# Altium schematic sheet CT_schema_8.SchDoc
size 274 x 160 mm
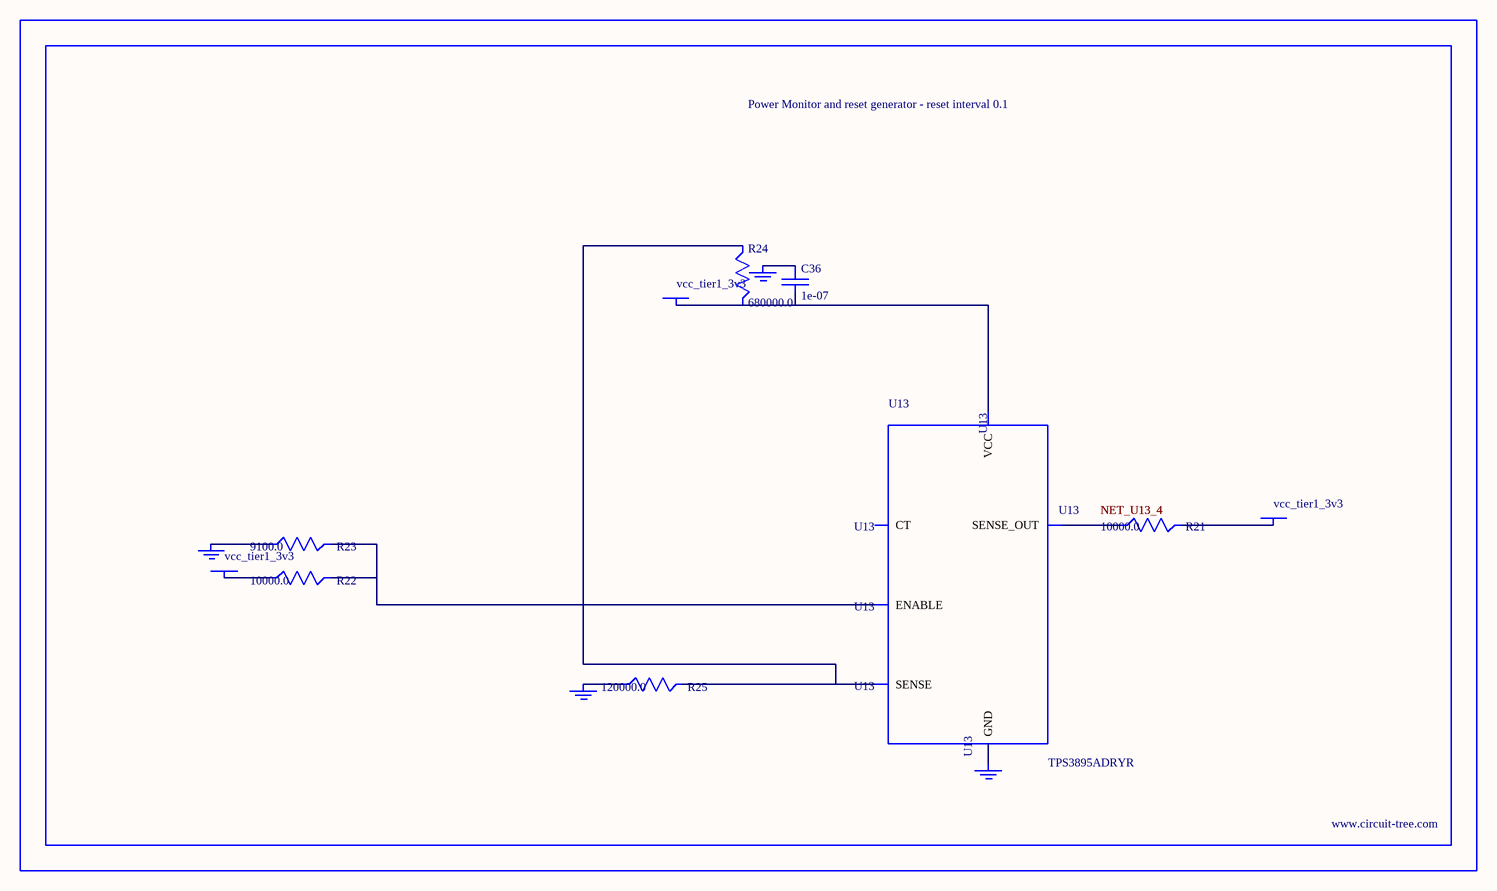
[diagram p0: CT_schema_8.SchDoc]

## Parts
BORDER7  (no value)
C36  1e-07  [C0402]
GND_INSTANCE_7_0  (no value)
GND_INSTANCE_7_1  (no value)
GND_INSTANCE_7_2  (no value)
GND_INSTANCE_7_3  (no value)
POWER_INSTANCE_7_0  vcc_tier1_3v3
POWER_INSTANCE_7_1  vcc_tier1_3v3
POWER_INSTANCE_7_2  vcc_tier1_3v3
R21  10000.0  [R0603]
R22  10000.0  [R0603]
R23  9100.0  [R0603]
R24  680000.0  [R0603]
R25  120000.0  [R0603]
U13  TPS3895ADRYR  [SON-6]

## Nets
NetC36_1: C36.1 GND_INSTANCE_7_2.0(GND)
NetC36_2: C36.2 POWER_INSTANCE_7_2.0(PWR) R24.2 U13.6(VCC)
NetGND_INSTANCE_7_0_0: GND_INSTANCE_7_0.0(GND) R23.1
NetGND_INSTANCE_7_1_0: GND_INSTANCE_7_1.0(GND) R25.1
NetGND_INSTANCE_7_3_0: GND_INSTANCE_7_3.0(GND) U13.2(GND)
NetPOWER_INSTANCE_7_0_0: POWER_INSTANCE_7_0.0(PWR) R22.1
NetPOWER_INSTANCE_7_1_0: POWER_INSTANCE_7_1.0(PWR) R21.2
NetR21_1: R21.1 U13.4(SENSE_OUT)
NetR22_2: R22.2 R23.2 U13.1(ENABLE)
NetR24_1: R24.1 R25.2 U13.3(SENSE)

Not connected (* = marked no-connect by the designer): U13 5(CT)

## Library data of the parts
BORDER7 = BORDER_PAGE7
C36 = C0402C104K3RACTU
GND_INSTANCE_7_0-GND_INSTANCE_7_3 = GND
POWER_INSTANCE_7_0-POWER_INSTANCE_7_2 = PWR
R21 R22 = RC0603JR-0710KL
R23 = RC0603JR-079K1L
R24 = RC0603JR-07680KL
R25 = RC0603JR-07120KL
